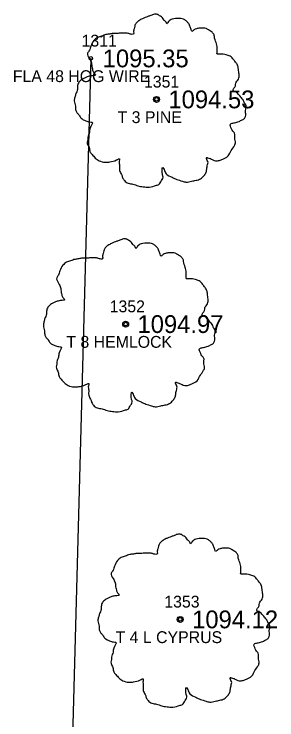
# Model space of a CAD drawing. Extents: x 1539151 to 1541799, y 1198646 to 1201165.
# Drawn here: x 1539670.3 to 1539692.5, y 1199406.9 to 1199466.5 of the extents above; entities that cross this region are included whole.
import ezdxf

# ---------------------------------------------------------------- set-up
doc = ezdxf.new("R2010")
doc.units = 0
for name, color, linetype in [('RD_EX_Fence_Other', 7, 'Continuous'), ('RD_EX_Fence_Other_txCode', 7, 'Continuous'), ('RD_EX_TX_Fence_Other_ELEV', 7, 'Continuous'), ('RD_EX_TX_VEG_ELEV', 7, 'Continuous'), ('RD_EX_VEG', 7, 'Continuous'), ('RD_EX_VEG_txCode', 7, 'Continuous'), ('RD_SMD_Locator', 7, 'Continuous')]:
    doc.layers.add(name, color=color, linetype=linetype)

msp = doc.modelspace()

# ---------------------------------------------------------------- linework, layer by layer
at = {"layer": 'RD_EX_Fence_Other'}
msp.add_line((1539676.762, 1199462.718), (1539674.613, 1199383.766), dxfattribs=at)
at = {"layer": 'RD_EX_VEG'}
for centre, radius in [((1539682.308, 1199459.256), 0.25), ((1539682.295, 1199459.237), 0.0001), ((1539679.699, 1199440.284), 0.25), ((1539679.686, 1199440.265), 0.0001), ((1539684.306, 1199415.35), 0.25), ((1539684.293, 1199415.331), 0.0001)]:
    msp.add_circle(centre, radius, dxfattribs=at)
for points in [[(1539682.44, 1199466.423), (1539682.14, 1199466.448), (1539681.815, 1199466.348), (1539681.565, 1199466.248), (1539681.34, 1199466.173), (1539681.115, 1199466.073), (1539680.815, 1199465.899), (1539680.59, 1199465.699), (1539680.465, 1199465.449), (1539680.415, 1199465.224), (1539680.365, 1199464.949), (1539680.365, 1199464.774), (1539680.241, 1199464.749), (1539680.091, 1199464.774), (1539679.841, 1199464.849), (1539679.591, 1199464.849), (1539679.341, 1199464.849), (1539678.991, 1199464.824), (1539678.641, 1199464.824), (1539678.366, 1199464.774), (1539678.041, 1199464.724), (1539677.667, 1199464.599), (1539677.317, 1199464.474), (1539677.017, 1199464.224), (1539676.767, 1199463.75), (1539676.642, 1199463.4), (1539676.492, 1199463.15), (1539676.642, 1199462.7), (1539676.817, 1199462.35), (1539676.842, 1199462.15), (1539676.917, 1199461.725), (1539677.017, 1199461.501), (1539677.142, 1199461.301), (1539677.067, 1199461.276), (1539676.692, 1199461.226), (1539676.392, 1199461.126), (1539675.967, 1199460.901), (1539675.742, 1199460.676), (1539675.642, 1199460.351), (1539675.618, 1199460.001), (1539675.518, 1199459.801), (1539675.443, 1199459.526), (1539675.418, 1199459.451), (1539675.368, 1199459.127), (1539675.468, 1199458.677), (1539675.493, 1199458.327), (1539675.618, 1199458.102), (1539675.767, 1199457.927), (1539675.942, 1199457.677), (1539676.342, 1199457.452), (1539676.667, 1199457.352), (1539676.867, 1199457.327), (1539676.692, 1199456.828), (1539676.642, 1199456.478), (1539676.517, 1199456.078), (1539676.517, 1199456.003), (1539676.467, 1199455.528), (1539676.617, 1199455.203), (1539676.692, 1199454.828), (1539676.867, 1199454.604), (1539677.142, 1199454.304), (1539677.467, 1199454.079), (1539677.967, 1199453.954), (1539678.366, 1199453.979), (1539678.941, 1199454.154), (1539679.191, 1199454.229), (1539679.166, 1199454.054), (1539679.191, 1199453.679), (1539679.191, 1199453.254), (1539679.341, 1199452.929), (1539679.441, 1199452.654), (1539679.591, 1199452.404), (1539679.916, 1199452.18), (1539680.315, 1199452.105), (1539680.74, 1199451.955), (1539681.19, 1199451.88), (1539681.69, 1199451.855), (1539682.29, 1199452.005), (1539682.564, 1199452.13), (1539682.664, 1199452.305), (1539682.864, 1199452.679), (1539682.814, 1199452.904), (1539682.839, 1199453.504), (1539682.939, 1199453.329), (1539683.114, 1199452.979), (1539683.614, 1199452.679), (1539684.014, 1199452.504), (1539684.489, 1199452.354), (1539684.789, 1199452.28), (1539685.263, 1199452.354), (1539685.638, 1199452.429), (1539686.013, 1199452.554), (1539686.313, 1199452.829), (1539686.488, 1199453.104), (1539686.538, 1199453.379), (1539686.613, 1199453.754), (1539686.663, 1199453.929)], [(1539686.663, 1199453.929), (1539686.588, 1199454.104), (1539686.538, 1199454.354), (1539686.613, 1199454.329), (1539686.788, 1199454.279), (1539687.063, 1199454.154), (1539687.287, 1199454.079), (1539687.612, 1199454.104), (1539687.887, 1199454.204), (1539688.337, 1199454.479), (1539688.612, 1199454.953), (1539688.887, 1199455.353), (1539688.962, 1199455.678), (1539688.912, 1199455.903), (1539688.887, 1199456.403), (1539688.687, 1199456.653), (1539688.637, 1199456.778), (1539688.537, 1199457.177), (1539688.612, 1199457.227), (1539688.887, 1199457.277), (1539689.262, 1199457.402), (1539689.536, 1199457.527), (1539689.761, 1199457.702), (1539689.836, 1199457.927), (1539689.811, 1199458.327), (1539689.861, 1199458.727), (1539689.786, 1199458.877), (1539689.686, 1199459.027), (1539689.611, 1199459.227), (1539689.461, 1199459.376), (1539689.362, 1199459.526), (1539689.262, 1199459.626), (1539689.137, 1199459.776), (1539688.962, 1199459.901), (1539688.812, 1199459.951), (1539688.762, 1199460.101), (1539688.912, 1199460.301), (1539688.962, 1199460.401), (1539688.987, 1199460.626), (1539689.212, 1199460.976), (1539689.262, 1199461.376), (1539689.212, 1199461.8), (1539689.162, 1199462.075), (1539689.012, 1199462.35), (1539688.812, 1199462.6), (1539688.687, 1199462.775), (1539688.512, 1199462.9), (1539688.187, 1199463.025), (1539687.937, 1199463.075), (1539687.587, 1199463.075), (1539687.387, 1199463.125), (1539687.412, 1199463.175), (1539687.412, 1199463.325), (1539687.412, 1199463.6), (1539687.337, 1199464.049), (1539687.187, 1199464.549), (1539687.187, 1199464.574), (1539687.087, 1199464.824), (1539686.863, 1199465.024), (1539686.688, 1199465.124), (1539686.488, 1199465.249), (1539686.238, 1199465.274), (1539685.938, 1199465.274), (1539685.663, 1199465.224), (1539685.463, 1199465.124), (1539685.288, 1199464.999), (1539685.213, 1199465.149), (1539685.113, 1199465.449), (1539685.063, 1199465.599), (1539684.913, 1199465.774), (1539684.689, 1199465.974), (1539684.239, 1199466.098), (1539683.614, 1199466.024), (1539683.314, 1199465.824), (1539683.164, 1199465.649), (1539683.114, 1199465.774), (1539682.914, 1199465.974), (1539682.814, 1199466.148), (1539682.639, 1199466.273), (1539682.49, 1199466.373), (1539682.39, 1199466.423)], [(1539679.831, 1199447.451), (1539679.531, 1199447.476), (1539679.206, 1199447.376), (1539678.956, 1199447.276), (1539678.731, 1199447.201), (1539678.506, 1199447.101), (1539678.206, 1199446.926), (1539677.981, 1199446.726), (1539677.856, 1199446.476), (1539677.806, 1199446.252), (1539677.757, 1199445.977), (1539677.757, 1199445.802), (1539677.632, 1199445.777), (1539677.482, 1199445.802), (1539677.232, 1199445.877), (1539676.982, 1199445.877), (1539676.732, 1199445.877), (1539676.382, 1199445.852), (1539676.032, 1199445.852), (1539675.757, 1199445.802), (1539675.433, 1199445.752), (1539675.058, 1199445.627), (1539674.708, 1199445.502), (1539674.408, 1199445.252), (1539674.158, 1199444.777), (1539674.033, 1199444.427), (1539673.883, 1199444.177), (1539674.033, 1199443.728), (1539674.208, 1199443.378), (1539674.233, 1199443.178), (1539674.308, 1199442.753), (1539674.408, 1199442.528), (1539674.533, 1199442.328), (1539674.458, 1199442.303), (1539674.083, 1199442.253), (1539673.783, 1199442.153), (1539673.358, 1199441.928), (1539673.134, 1199441.704), (1539673.034, 1199441.379), (1539673.009, 1199441.029), (1539672.909, 1199440.829), (1539672.834, 1199440.554), (1539672.809, 1199440.479), (1539672.759, 1199440.154), (1539672.859, 1199439.704), (1539672.884, 1199439.355), (1539673.009, 1199439.13), (1539673.159, 1199438.955), (1539673.333, 1199438.705), (1539673.733, 1199438.48), (1539674.058, 1199438.38), (1539674.258, 1199438.355), (1539674.083, 1199437.855), (1539674.033, 1199437.505), (1539673.908, 1199437.106), (1539673.908, 1199437.031), (1539673.858, 1199436.556), (1539674.008, 1199436.231), (1539674.083, 1199435.856), (1539674.258, 1199435.631), (1539674.533, 1199435.331), (1539674.858, 1199435.106), (1539675.358, 1199434.981), (1539675.757, 1199435.006), (1539676.332, 1199435.181), (1539676.582, 1199435.256), (1539676.557, 1199435.081), (1539676.582, 1199434.707), (1539676.582, 1199434.282), (1539676.732, 1199433.957), (1539676.832, 1199433.682), (1539676.982, 1199433.432), (1539677.307, 1199433.207), (1539677.707, 1199433.132), (1539678.131, 1199432.982), (1539678.581, 1199432.907), (1539679.081, 1199432.882), (1539679.681, 1199433.032), (1539679.956, 1199433.157), (1539680.056, 1199433.332), (1539680.255, 1199433.707), (1539680.205, 1199433.932), (1539680.23, 1199434.532), (1539680.33, 1199434.357), (1539680.505, 1199434.007), (1539681.005, 1199433.707), (1539681.405, 1199433.532), (1539681.88, 1199433.382), (1539682.18, 1199433.307), (1539682.654, 1199433.382), (1539683.029, 1199433.457), (1539683.404, 1199433.582), (1539683.704, 1199433.857), (1539683.879, 1199434.132), (1539683.929, 1199434.407), (1539684.004, 1199434.782), (1539684.054, 1199434.956)], [(1539684.054, 1199434.956), (1539683.979, 1199435.131), (1539683.929, 1199435.381), (1539684.004, 1199435.356), (1539684.179, 1199435.306), (1539684.454, 1199435.181), (1539684.679, 1199435.106), (1539685.003, 1199435.131), (1539685.278, 1199435.231), (1539685.728, 1199435.506), (1539686.003, 1199435.981), (1539686.278, 1199436.381), (1539686.353, 1199436.706), (1539686.303, 1199436.931), (1539686.278, 1199437.43), (1539686.078, 1199437.68), (1539686.028, 1199437.805), (1539685.928, 1199438.205), (1539686.003, 1199438.255), (1539686.278, 1199438.305), (1539686.653, 1199438.43), (1539686.928, 1199438.555), (1539687.152, 1199438.73), (1539687.227, 1199438.955), (1539687.202, 1199439.355), (1539687.252, 1199439.754), (1539687.177, 1199439.904), (1539687.077, 1199440.054), (1539687.002, 1199440.254), (1539686.853, 1199440.404), (1539686.753, 1199440.554), (1539686.653, 1199440.654), (1539686.528, 1199440.804), (1539686.353, 1199440.929), (1539686.203, 1199440.979), (1539686.153, 1199441.129), (1539686.303, 1199441.329), (1539686.353, 1199441.429), (1539686.378, 1199441.654), (1539686.603, 1199442.003), (1539686.653, 1199442.403), (1539686.603, 1199442.828), (1539686.553, 1199443.103), (1539686.403, 1199443.378), (1539686.203, 1199443.628), (1539686.078, 1199443.803), (1539685.903, 1199443.928), (1539685.578, 1199444.053), (1539685.328, 1199444.102), (1539684.978, 1199444.102), (1539684.778, 1199444.152), (1539684.803, 1199444.202), (1539684.803, 1199444.352), (1539684.803, 1199444.627), (1539684.728, 1199445.077), (1539684.579, 1199445.577), (1539684.579, 1199445.602), (1539684.479, 1199445.852), (1539684.254, 1199446.052), (1539684.079, 1199446.152), (1539683.879, 1199446.277), (1539683.629, 1199446.302), (1539683.329, 1199446.302), (1539683.054, 1199446.252), (1539682.854, 1199446.152), (1539682.679, 1199446.027), (1539682.604, 1199446.177), (1539682.504, 1199446.476), (1539682.454, 1199446.626), (1539682.305, 1199446.801), (1539682.08, 1199447.001), (1539681.63, 1199447.126), (1539681.005, 1199447.051), (1539680.705, 1199446.851), (1539680.555, 1199446.676), (1539680.505, 1199446.801), (1539680.305, 1199447.001), (1539680.205, 1199447.176), (1539680.031, 1199447.301), (1539679.881, 1199447.401), (1539679.781, 1199447.451)], [(1539684.438, 1199422.518), (1539684.138, 1199422.543), (1539683.813, 1199422.443), (1539683.563, 1199422.343), (1539683.338, 1199422.268), (1539683.114, 1199422.168), (1539682.814, 1199421.993), (1539682.589, 1199421.793), (1539682.464, 1199421.543), (1539682.414, 1199421.318), (1539682.364, 1199421.043), (1539682.364, 1199420.868), (1539682.239, 1199420.843), (1539682.089, 1199420.868), (1539681.839, 1199420.943), (1539681.589, 1199420.943), (1539681.339, 1199420.943), (1539680.989, 1199420.918), (1539680.64, 1199420.918), (1539680.365, 1199420.868), (1539680.04, 1199420.818), (1539679.665, 1199420.693), (1539679.315, 1199420.568), (1539679.015, 1199420.318), (1539678.765, 1199419.844), (1539678.64, 1199419.494), (1539678.491, 1199419.244), (1539678.64, 1199418.794), (1539678.815, 1199418.444), (1539678.84, 1199418.244), (1539678.915, 1199417.82), (1539679.015, 1199417.595), (1539679.14, 1199417.395), (1539679.065, 1199417.37), (1539678.69, 1199417.32), (1539678.391, 1199417.22), (1539677.966, 1199416.995), (1539677.741, 1199416.77), (1539677.641, 1199416.445), (1539677.616, 1199416.095), (1539677.516, 1199415.895), (1539677.441, 1199415.621), (1539677.416, 1199415.546), (1539677.366, 1199415.221), (1539677.466, 1199414.771), (1539677.491, 1199414.421), (1539677.616, 1199414.196), (1539677.766, 1199414.021), (1539677.941, 1199413.771), (1539678.341, 1199413.546), (1539678.665, 1199413.446), (1539678.865, 1199413.422), (1539678.69, 1199412.922), (1539678.64, 1199412.572), (1539678.516, 1199412.172), (1539678.516, 1199412.097), (1539678.466, 1199411.622), (1539678.615, 1199411.297), (1539678.69, 1199410.923), (1539678.865, 1199410.698), (1539679.14, 1199410.398), (1539679.465, 1199410.173), (1539679.965, 1199410.048), (1539680.365, 1199410.073), (1539680.94, 1199410.248), (1539681.189, 1199410.323), (1539681.164, 1199410.148), (1539681.189, 1199409.773), (1539681.189, 1199409.348), (1539681.339, 1199409.023), (1539681.439, 1199408.749), (1539681.589, 1199408.499), (1539681.914, 1199408.274), (1539682.314, 1199408.199), (1539682.739, 1199408.049), (1539683.189, 1199407.974), (1539683.688, 1199407.949), (1539684.288, 1199408.099), (1539684.563, 1199408.224), (1539684.663, 1199408.399), (1539684.863, 1199408.774), (1539684.813, 1199408.998), (1539684.838, 1199409.598), (1539684.938, 1199409.423), (1539685.113, 1199409.073), (1539685.612, 1199408.774), (1539686.012, 1199408.599), (1539686.487, 1199408.449), (1539686.787, 1199408.374), (1539687.262, 1199408.449), (1539687.637, 1199408.524), (1539688.011, 1199408.649), (1539688.311, 1199408.923), (1539688.486, 1199409.198), (1539688.536, 1199409.473), (1539688.611, 1199409.848), (1539688.661, 1199410.023)], [(1539688.661, 1199410.023), (1539688.586, 1199410.198), (1539688.536, 1199410.448), (1539688.611, 1199410.423), (1539688.786, 1199410.373), (1539689.061, 1199410.248), (1539689.286, 1199410.173), (1539689.611, 1199410.198), (1539689.886, 1199410.298), (1539690.335, 1199410.573), (1539690.61, 1199411.048), (1539690.885, 1199411.447), (1539690.96, 1199411.772), (1539690.91, 1199411.997), (1539690.885, 1199412.497), (1539690.685, 1199412.747), (1539690.635, 1199412.872), (1539690.535, 1199413.272), (1539690.61, 1199413.322), (1539690.885, 1199413.372), (1539691.26, 1199413.496), (1539691.535, 1199413.621), (1539691.76, 1199413.796), (1539691.835, 1199414.021), (1539691.81, 1199414.421), (1539691.86, 1199414.821), (1539691.785, 1199414.971), (1539691.685, 1199415.121), (1539691.61, 1199415.321), (1539691.46, 1199415.471), (1539691.36, 1199415.621), (1539691.26, 1199415.72), (1539691.135, 1199415.87), (1539690.96, 1199415.995), (1539690.81, 1199416.045), (1539690.76, 1199416.195), (1539690.91, 1199416.395), (1539690.96, 1199416.495), (1539690.985, 1199416.72), (1539691.21, 1199417.07), (1539691.26, 1199417.47), (1539691.21, 1199417.895), (1539691.16, 1199418.169), (1539691.01, 1199418.444), (1539690.81, 1199418.694), (1539690.685, 1199418.869), (1539690.51, 1199418.994), (1539690.185, 1199419.119), (1539689.936, 1199419.169), (1539689.586, 1199419.169), (1539689.386, 1199419.219), (1539689.411, 1199419.269), (1539689.411, 1199419.419), (1539689.411, 1199419.694), (1539689.336, 1199420.144), (1539689.186, 1199420.643), (1539689.186, 1199420.668), (1539689.086, 1199420.918), (1539688.861, 1199421.118), (1539688.686, 1199421.218), (1539688.486, 1199421.343), (1539688.236, 1199421.368), (1539687.936, 1199421.368), (1539687.662, 1199421.318), (1539687.462, 1199421.218), (1539687.287, 1199421.093), (1539687.212, 1199421.243), (1539687.112, 1199421.543), (1539687.062, 1199421.693), (1539686.912, 1199421.868), (1539686.687, 1199422.068), (1539686.237, 1199422.193), (1539685.612, 1199422.118), (1539685.313, 1199421.918), (1539685.163, 1199421.743), (1539685.113, 1199421.868), (1539684.913, 1199422.068), (1539684.813, 1199422.243), (1539684.638, 1199422.368), (1539684.488, 1199422.468), (1539684.388, 1199422.518)]]:
    msp.add_spline(points, degree=3, dxfattribs=at)
at = {"layer": 'RD_SMD_Locator'}
for centre in [(1539676.762, 1199462.718), (1539682.308, 1199459.256), (1539679.699, 1199440.284), (1539684.306, 1199415.35)]:
    msp.add_circle(centre, 0.15, dxfattribs=at)

# ---------------------------------------------------------------- texts
at = {"layer": 'RD_EX_Fence_Other_txCode'}
for s, p in [('1311', (1539675.982, 1199463.718)), ('FLA 48 HOG WIRE', (1539670.183, 1199460.718))]:
    msp.add_text(s, height=1, dxfattribs=at).set_placement(p)
at = {"layer": 'RD_EX_TX_Fence_Other_ELEV'}
msp.add_text('1095.35', height=1.5, dxfattribs=at).set_placement((1539677.762, 1199461.968))
at = {"layer": 'RD_EX_TX_VEG_ELEV'}
for s, p in [('1094.53', (1539683.308, 1199458.506)), ('1094.97', (1539680.699, 1199439.534)), ('1094.12', (1539685.306, 1199414.6))]:
    msp.add_text(s, height=1.5, dxfattribs=at).set_placement(p)
at = {"layer": 'RD_EX_VEG_txCode'}
for s, p in [('1351', (1539681.245, 1199460.256)), ('T 3 PINE', (1539679.02, 1199457.256)), ('1352', (1539678.352, 1199441.284)), ('T 8 HEMLOCK', (1539674.699, 1199438.284)), ('1353', (1539682.96, 1199416.35)), ('T 4 L CYPRUS', (1539678.849, 1199413.35))]:
    msp.add_text(s, height=1, dxfattribs=at).set_placement(p)

doc.saveas('drawing.dxf')
